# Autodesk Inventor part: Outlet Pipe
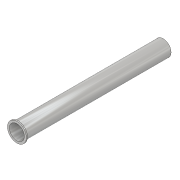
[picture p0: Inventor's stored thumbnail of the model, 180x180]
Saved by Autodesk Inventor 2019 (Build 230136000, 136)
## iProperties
Created: 2019-11
Part Number: Outlet Pipe
Material: Steel, Carbon
Document SubType Name: Modeling
Designer: Admin
Density: 7.85 g/cm^3
Appearance: Semi-Polished
Author: Admin
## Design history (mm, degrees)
sketch "Sketch1"
  geometry: C1 r 127.254 at (0, 0); C2 r 136.525 at (0, 0); 1 further point
  constraints: 2 centre point, 2 coincident
  dimensions: "d0" = 254.508 diameter of C1; "d1" = 273.05 diameter of C2
extrude "Extrusion1" new body sketch "Sketch1" distance "d2" = 2500; taper "d3" = 0 deg
sketch "Sketch2"
  geometry: C1 r 162 at (0, 0); C2 r 136.525 at (0, 0) reference; 1 further point
  constraints: 1 centre point, 1 coincident
  dimensions: "d4" = 324 diameter of C1
extrude "Extrusion2" join sketch "Sketch2" distance "d5" = 20; taper "d6" = 0 deg
body "Solid1"
